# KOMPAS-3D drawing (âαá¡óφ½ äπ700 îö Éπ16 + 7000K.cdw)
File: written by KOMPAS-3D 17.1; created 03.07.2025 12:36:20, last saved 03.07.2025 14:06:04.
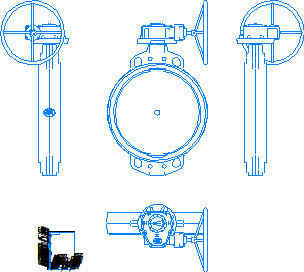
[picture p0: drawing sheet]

Sheet 1: A4, portrait

Title block, sheet 1: sheets: 1; sheet format: A4; stored path: \\adlc.lan\data\АДЛ_ПКД\3D-модели\ADL production\Дисковые поворотные затворы ГРАНВЭЛ\межфланцевый с китайским редуктором Ру16\KOMPAS 2D\Гранвэл Ду700 МФ Ру16 + 7000K.cdw

Views: Вид 1, Спереди, Проекционный вид 3, Проекционный вид 4
Referenced files in \\adlc.lan\data\АДЛ_ПКД\3D-модели\ADL production\Дисковые поворотные затворы ГРАНВЭЛ\межфланцевый с китайским редуктором Ру16\KOMPAS 3D\: Гранвэл Ду700 МФ Ру16 + 7000K.m3d
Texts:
  Andrey
  АДЛ
Dimensions and other numbers on the sheet: 1:1; 1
